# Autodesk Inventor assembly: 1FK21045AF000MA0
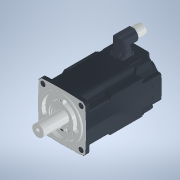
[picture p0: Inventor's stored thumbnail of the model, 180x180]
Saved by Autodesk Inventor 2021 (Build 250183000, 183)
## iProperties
Category: PARTsolutions
Created: 2026-06
Part Number: 1FK21045AF000MA0
Catalog Web Link: www.3dfindit.com
Description: 1FK21045AF000MA0-Servo synchronous motor
Document SubType Name: Assembly
Designer: psAdmin
Mass: 724.86 g
Surface Area: 1070.93 cm^2
Volume: 724.86 cm^3
Density: 1 g/cm^3
Title: 1FK21045AF000MA0
Author: Cadenas PARTsolutions
Comments: Servo synchronous motor
PSOL_IDENT_0: {$CADENAS_DATA/23d-libs/siemens_ag/_cat_/8b/0a/1fk21045af000ma0.prj},193 {STYP=ASS},{VTYP=3D},{NB=1F
PSOL_IDENT_1: K21045AF000MA0},{LINA=1FK21045AF000MA0},{NN=1FK21045AF000MA0},{DATE=19.08.2025 14:00:48},{GEOMDATE=3
PSOL_IDENT_2: 0.07.2025 02:00:28},{VERSION=},{LINEID=10},{WBVAR=},{WBNUMERIC=}  {NB=1FK21045AF000MA0},{LINA=1FK210
PSOL_IDENT_3: 45AF000MA0},{KT=DUMMY},{PREVIEW=../../../_pool_/a9/69/p_d211_xx_00818j.png},{DESCSHORT=SIMOTICS S-1F
PSOL_IDENT_4: K2 HD, SINAMICS S210 3AC 400V-480V, 2.4 Nm, 3000 rpm},{DESCLONG=SIMOTICS S-1FK2 HD servo motor M0=2.
PSOL_IDENT_5: 4 Nm; PN = 0.75 kW at nN=3000 rpm (380-480 V); PN = 0.375 kW at nN=1500 rpm (200-240 V); degree of p
PSOL_IDENT_6: rotection IP64; cylindrical shaft D19x40mm; absolute encoder 22-bit + 12-bit multiturn (encoder AM22
PSOL_IDENT_7: DQC); with OCC interface; plug size M17, rotatable; SIMOTICS S-1FK2 servomotorfor a wide range of us
PSOL_IDENT_8: es in industrial environments. SIMOTICS S‑1FK2 servomotors are compact synchronous motors with a hig
PSOL_IDENT_9: h dynamic performance that set themselves apart as a result of their high power density, degree of p
PSOL_IDENT_10: rotection and overload capability. The motors are available in two variants: as High Dynamic variant
PSOL_IDENT_11: (highest dynamic performance as a result of the low intrinsic moment of inertia for applications de
PSOL_IDENT_12: manding a high dynamic performance with low moved masses) - and as Compact variant (precise and stab
PSOL_IDENT_13: le closed-loop control for medium up to large moved masses as a result of a medium intrinsic moment
PSOL_IDENT_14: of inertia). SIMOTICSS‑1FK2 servomotors fully exploit their strengths in a system with the SINAMICSS
PSOL_IDENT_15: 210 frequency converter and simple connection using the one cable connection (OCC). Advantages inclu
PSOL_IDENT_16: de the short control and positioning times, fast and precise correction of disturbing quantities as
PSOL_IDENT_17: well as stable control with a high dynamic performance. The servo motors can be configured to addres
PSOL_IDENT_18: s a wide range of requirements. For example with and without holding brake, IP64 or IP65 degree of p
PSOL_IDENT_19: rotection, singleturn or multiturn absolute encoders - to name just a few. Further, the servomotors
PSOL_IDENT_20: are available in different shaft heights extending from 20 to 100. A shaft sealing ring is available
PSOL_IDENT_21: to achieve an IP65 degree of protection and for subsequent mounting at the motor or as spare part.
PSOL_IDENT_22: SIMOTICS - the optimum motor for each and every motion control application.},{INTNO=195125050112},{S
PSOL_IDENT_23: UPPLIERALTNO=1FK2104-5AF00-0MA0},{MANUID=1FK21045AF000MA0},{MANUNAME=Siemens},{MANUTYPEDESC=Synchron
PSOL_IDENT_24: ous motor 1FK2-HD 2.4 NM},{AAU732=SIMOTICS},{AAO057=S-1FK2},{AAU734=SIMOTICS S-1FK2 HD servo motor M
PSOL_IDENT_25: 0=2.4 Nm; PN = 0.75 kW at nN=3000 rpm (380-480 V); PN = 0.375 kW at nN=1500 rpm (200-240 V); degree
PSOL_IDENT_26: of protection IP64; cylindrical shaft D19x40mm; absolute encoder 22-bit + 12-bit multiturn (encoder
PSOL_IDENT_27: AM22DQC); with OCC interface; plug size M17, rotatable;},{AAW338=Synchronous motor 1FK2-HD 2.4 NM},{
PSOL_IDENT_28: AAO742=SIMOTICS},{AAO663=4042948692912},{NOCUPEROU=1},{PRICEQUANTITY=1},{QUANTITYMIN=1},{QUANTITYINT=
PSOL_IDENT_29: 1},{CTN=85015100},{COO=DE},{AAO676=1FK2104-5AF00-0MA0},{AAO677=Siemens AG},{ORDERUNIT=C62},{CONTENTU
PSOL_IDENT_30: NIT=C62}
NB: 1FK21045AF000MA0
NN: 1FK21045AF000MA0
NT: Servo synchronous motor
NBSYN: $MANUID.
LINA: 1FK21045AF000MA0
CATALOG: SIEMENS
PREVIEW: ../../../_pool_/a9/69/p_d211_xx_00818j.png
DESCSHORT: SIMOTICS S-1FK2 HD, SINAMICS S210 3AC 400V-480V, 2.4 Nm, 3000 rpm
DESCLONG: SIMOTICS S-1FK2 HD servo motor M0=2.4 Nm; PN = 0.75 kW at nN=3000 rpm (380-480 V); PN = 0.375 kW at nN=1500 rpm (200-240 V); degree of protection IP64; cylindri
INTNO: 195125050112
SUPPLIERALTNO: 1FK2104-5AF00-0MA0
MANUID: 1FK21045AF000MA0
MANUNAME: Siemens
MANUTYPEDESC: Synchronous motor 1FK2-HD 2.4 NM
AAU732: SIMOTICS
AAO057: S-1FK2
AAU734: SIMOTICS S-1FK2 HD servo motor M0=2.4 Nm; PN = 0.75 kW at nN=3000 rpm (380-480 V); PN = 0.375 kW at nN=1500 rpm (200-240 V); degree of protection IP64; cylindri
AAW338: Synchronous motor 1FK2-HD 2.4 NM
AAO742: SIMOTICS
AAO663: 4042948692912.0
NOCUPEROU: 1
PRICEQUANTITY: 1
QUANTITYMIN: 1
QUANTITYINT: 1
CTN: 85015100
COO: DE
ARTICLENO: 1FK21045AF000MA0
BOMINFO: 1FK21045AF000MA0
CREATOR: CADENAS GmbH
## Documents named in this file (24)
- e:\temp\worker_COMMON_23\temp\tmp_3608_6_clmqH\format_0\1FK21045AF000MA0.iam
- e:\temp\worker_COMMON_23\temp\tmp_3608_6_clmqH\format_0\1FK21045AF000MA0_PART1.ipt
- e:\temp\worker_COMMON_23\temp\tmp_3608_6_clmqH\format_0\1FK21045AF000MA0_PART2.ipt
- e:\temp\worker_COMMON_23\temp\tmp_3608_6_clmqH\format_0\1FK21045AF000MA0_PART3.ipt
- e:\temp\worker_COMMON_23\temp\tmp_3608_6_clmqH\format_0\1FK21045AF000MA0_PART4.ipt
- e:\temp\worker_COMMON_23\temp\tmp_3608_6_clmqH\format_0\1FK21045AF000MA0_PART5.ipt
- e:\temp\worker_COMMON_23\temp\tmp_3608_6_clmqH\format_0\1FK21045AF000MA0_PART6.ipt
- e:\temp\worker_COMMON_23\temp\tmp_3608_6_clmqH\format_0\1FK21045AF000MA0_PART7.ipt
- e:\temp\worker_COMMON_23\temp\tmp_3608_6_clmqH\format_0\1FK21045AF000MA0_PART8.ipt
- e:\temp\worker_COMMON_23\temp\tmp_3608_6_clmqH\format_0\1FK21045AF000MA0_PART9.ipt
- e:\temp\worker_COMMON_23\temp\tmp_3608_6_clmqH\format_0\1FK21045AF000MA0_PART10.ipt
- e:\temp\worker_COMMON_23\temp\tmp_3608_6_clmqH\format_0\1FK21045AF000MA0_PART11.ipt
- e:\temp\worker_COMMON_23\temp\tmp_3608_6_clmqH\format_0\1FK21045AF000MA0_PART12.ipt
- e:\temp\worker_COMMON_23\temp\tmp_3608_6_clmqH\format_0\1FK21045AF000MA0_PART13.ipt
- e:\temp\worker_COMMON_23\temp\tmp_3608_6_clmqH\format_0\1FK21045AF000MA0_PART14.ipt
- e:\temp\worker_COMMON_23\temp\tmp_3608_6_clmqH\format_0\1FK21045AF000MA0_PART15.ipt
- e:\temp\worker_COMMON_23\temp\tmp_3608_6_clmqH\format_0\1FK21045AF000MA0_PART16.ipt
- e:\temp\worker_COMMON_23\temp\tmp_3608_6_clmqH\format_0\1FK21045AF000MA0_PART17.ipt
- e:\temp\worker_COMMON_23\temp\tmp_3608_6_clmqH\format_0\1FK21045AF000MA0_PART18.ipt
- e:\temp\worker_COMMON_23\temp\tmp_3608_6_clmqH\format_0\1FK21045AF000MA0_PART19.ipt
- e:\temp\worker_COMMON_23\temp\tmp_3608_6_clmqH\format_0\1FK21045AF000MA0_PART20.ipt
- e:\temp\worker_COMMON_23\temp\tmp_3608_6_clmqH\format_0\1FK21045AF000MA0_PART21.ipt
- e:\temp\worker_COMMON_23\temp\tmp_3608_6_clmqH\format_0\1FK21045AF000MA0_PART22.ipt
- e:\temp\worker_COMMON_23\temp\tmp_3608_6_clmqH\format_0\1FK21045AF000MA0_PART23.ipt
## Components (23 placed, 23 different names)
1. 1FK21045AF000MA0_PART1:1
2. 1FK21045AF000MA0_PART2:1
3. 1FK21045AF000MA0_PART3:1
4. 1FK21045AF000MA0_PART4:1
5. 1FK21045AF000MA0_PART5:1
6. 1FK21045AF000MA0_PART6:1
7. 1FK21045AF000MA0_PART7:1
8. 1FK21045AF000MA0_PART8:1
9. 1FK21045AF000MA0_PART9:1
10. 1FK21045AF000MA0_PART10:1
11. 1FK21045AF000MA0_PART11:1
12. 1FK21045AF000MA0_PART12:1
13. 1FK21045AF000MA0_PART13:1
14. 1FK21045AF000MA0_PART14:1
15. 1FK21045AF000MA0_PART15:1
16. 1FK21045AF000MA0_PART16:1
17. 1FK21045AF000MA0_PART17:1
18. 1FK21045AF000MA0_PART18:1
19. 1FK21045AF000MA0_PART19:1
20. 1FK21045AF000MA0_PART20:1
21. 1FK21045AF000MA0_PART21:1
22. 1FK21045AF000MA0_PART22:1
23. 1FK21045AF000MA0_PART23:1
